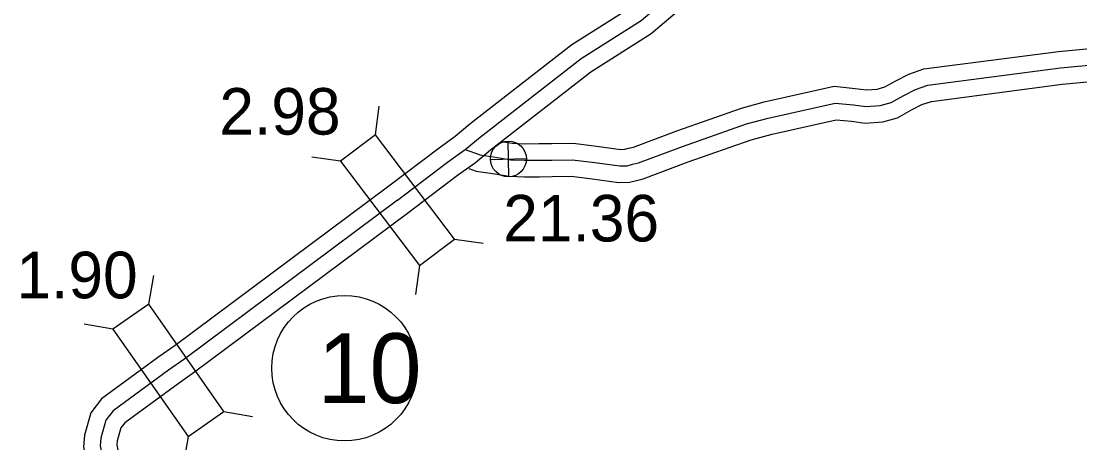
# Model space of a CAD drawing. Extents: x -83719 to 153526, y -11835 to 11446.
# Drawn here: x -3258.4 to -2938.4, y -16.9 to 110.6 of the extents above; entities that cross this region are included whole.
import ezdxf

# ---------------------------------------------------------------- set-up
doc = ezdxf.new("R2010")
doc.units = 0
for name, color, linetype in [('Level 10', 7, 'Continuous'), ('Level 20', 7, 'Continuous'), ('Level 25', 7, 'Continuous'), ('Level 26', 7, 'Continuous'), ('Level 27', 7, 'Continuous'), ('Level 58', 7, 'Continuous'), ('Level 59', 7, 'Continuous')]:
    doc.layers.add(name, color=color, linetype=linetype)

msp = doc.modelspace()

# ---------------------------------------------------------------- linework, layer by layer
at = {"layer": 'Level 10'}
for points in [[(-2979.45, 242.65), (-2990.74, 231.2), (-2993.59, 227.82), (-2996.41, 223.58), (-2998.11, 219.76), (-3018.44, 166.18), (-3020.1, 162.69), (-3021.9, 159.54), (-3022.67, 158.47), (-3035.99, 147.01), (-3073.93, 114.8), (-3091.99, 103.38), (-3122.81, 79.4), (-3127.24, 75.69), (-3132.47, 71.92), (-3147.67, 60.4)], [(-2972.33, 235.63), (-2983.34, 224.46), (-2985.58, 221.81), (-2987.62, 218.74), (-2988.86, 215.95), (-3009.23, 162.26), (-3011.23, 158.06), (-3013.48, 154.12), (-3015.25, 151.67), (-3029.49, 139.41), (-3067.99, 106.72), (-3086.24, 95.19), (-3116.53, 71.61), (-3121.09, 67.79), (-3126.52, 63.88), (-3141.63, 52.43)], [(-3113.25, 74.21), (-3109.9, 73.66), (-3106.14, 73.52), (-3101.89, 73.54), (-3098.01, 73.58), (-3091.57, 73.68), (-3085.19, 72.88), (-3077.18, 71.82), (-3075.89, 71.85), (-3074.78, 72.15), (-3073.29, 72.49), (-3060.24, 77.4), (-3040.67, 84.27), (-3033.85, 86.14), (-3012.69, 90.89), (-3006.25, 90.24), (-3002.92, 89.8), (-2999.66, 90.02), (-2997.36, 90.68), (-2993.96, 92.56), (-2990.04, 94.56), (-2985.51, 96.12), (-2944.83, 101.43), (-2909, 104.83)], [(-3123.03, 66.02), (-3120.89, 65.26), (-3115.19, 64.39), (-3110.89, 63.69), (-3106.3, 63.52), (-3101.81, 63.54), (-3097.88, 63.58), (-3092.12, 63.67), (-3086.46, 62.96), (-3077.74, 61.81), (-3074.49, 61.87), (-3072.36, 62.44), (-3070.39, 62.9), (-3056.82, 68), (-3037.69, 74.72), (-3031.43, 76.44), (-3012.08, 80.78), (-3007.41, 80.31), (-3003.25, 79.76), (-2997.92, 80.11), (-2993.51, 81.38), (-2989.26, 83.73), (-2986.12, 85.34), (-2983.22, 86.33), (-2943.71, 91.49), (-2906.81, 94.99)], [(-3147.64, 60.42), (-3211.85, 12.54), (-3216.8, 9.08), (-3234.14, -3.63), (-3237.39, -7.81), (-3239.28, -14.63), (-3239.51, -18.11), (-3236.23, -35.79), (-3233.72, -48.79), (-3224.68, -87.55), (-3225.34, -105.4), (-3226.36, -112.94), (-3227.07, -114.31), (-3229.55, -117.75), (-3232.76, -121.26), (-3234.53, -122.48), (-3236.78, -123.15), (-3240.47, -123.09), (-3245.58, -122.31), (-3249.04, -120.66)], [(-3141.66, 52.41), (-3206, 4.44), (-3210.98, 0.95), (-3227.1, -10.86), (-3228.28, -12.38), (-3229.37, -16.32), (-3229.45, -17.52), (-3226.4, -33.93), (-3223.94, -46.7), (-3214.63, -86.58), (-3215.37, -106.25), (-3216.68, -116.01), (-3218.54, -119.57), (-3221.77, -124.06), (-3226.14, -128.85), (-3230.16, -131.62), (-3235.4, -133.17), (-3241.31, -133.08), (-3245.56, -132.43)]]:
    msp.add_lwpolyline(points, dxfattribs=at)
at = {"layer": 'Level 20'}
for p, q in [((-3151.34, 76.18), (-3150.14, 84.9)), ((-3161.87, 68.21), (-3170.58, 69.42)), ((-3127.44, 44.62), (-3118.72, 43.41)), ((-3137.96, 36.65), (-3139.16, 27.93)), ((-3219.83, 25.02), (-3218.3, 33.69)), ((-3230.65, 17.46), (-3239.31, 18.99)), ((-3197.13, -7.43), (-3188.47, -8.96)), ((-3207.95, -14.99), (-3209.48, -23.66))]:
    msp.add_line(p, q, dxfattribs=at)
for points in [[(-3127.44, 44.62), (-3151.34, 76.18), (-3161.87, 68.21), (-3137.96, 36.65)], [(-3197.13, -7.43), (-3219.83, 25.02), (-3230.65, 17.46), (-3207.95, -14.99)]]:
    msp.add_lwpolyline(points, close=True, dxfattribs=at)
at = {"layer": 'Level 26'}
for p, q in [((-3110.98, 63.49), (-3111.23, 74.34)), ((-3116.53, 68.79), (-3105.68, 69.04))]:
    msp.add_line(p, q, dxfattribs=at)
msp.add_circle((-3111.11, 68.91), 5.43, dxfattribs=at)
at = {"layer": 'Level 27'}
msp.add_circle((-3160.66, 5.64), 22, dxfattribs=at)
at = {"layer": 'Level 59'}
for points in [[(-3144.65, 56.42), (-3129.49, 67.9), (-3124.16, 71.74), (-3119.67, 75.5), (-3089.11, 99.28), (-3070.96, 110.76), (-3032.74, 143.21), (-3018.96, 155.07), (-3017.69, 156.83), (-3015.66, 160.38), (-3013.84, 164.22), (-2993.48, 217.86), (-2992.01, 221.16), (-2989.58, 224.81), (-2987.04, 227.83), (-2975.89, 239.14)], [(-3124.16, 71.74), (-3119.66, 70.13), (-3114.41, 69.33), (-3110.39, 68.67), (-3106.22, 68.52), (-3101.85, 68.54), (-3097.95, 68.58), (-3091.84, 68.67), (-3085.82, 67.92), (-3077.46, 66.82), (-3075.19, 66.86), (-3073.57, 67.29), (-3071.84, 67.7), (-3058.53, 72.7), (-3039.18, 79.49), (-3032.64, 81.29), (-3012.38, 85.83), (-3006.83, 85.27), (-3003.09, 84.78), (-2998.79, 85.06), (-2995.44, 86.03), (-2991.61, 88.14), (-2988.08, 89.95), (-2984.36, 91.23), (-2944.27, 96.46), (-2907.9, 99.91)], [(-3144.65, 56.42), (-3208.92, 8.49), (-3213.89, 5.02), (-3230.62, -7.25), (-3232.83, -10.1), (-3234.33, -15.47), (-3234.48, -17.82), (-3231.31, -34.86), (-3228.83, -47.75), (-3219.66, -87.06), (-3220.36, -105.83), (-3221.52, -114.47), (-3222.81, -116.94), (-3225.66, -120.9), (-3229.45, -125.05), (-3232.34, -127.05), (-3236.09, -128.16), (-3240.89, -128.09), (-3247.08, -127.14), (-3252.43, -124.57)]]:
    msp.add_lwpolyline(points, dxfattribs=at)

# ---------------------------------------------------------------- texts
at = {"layer": 'Level 25'}
msp.add_text('21.36', height=14.08, dxfattribs=at).set_placement((-3112.69, 43.96))
at = {"layer": 'Level 27'}
msp.add_text('10', height=21.12, dxfattribs=at).set_placement((-3168.8, -4.92))
at = {"layer": 'Level 58'}
for s, p in [('2.98', (-3198.49, 76.27)), ('1.90', (-3259.83, 26.78))]:
    msp.add_text(s, height=14.08, dxfattribs=at).set_placement(p)

doc.saveas('drawing.dxf')
